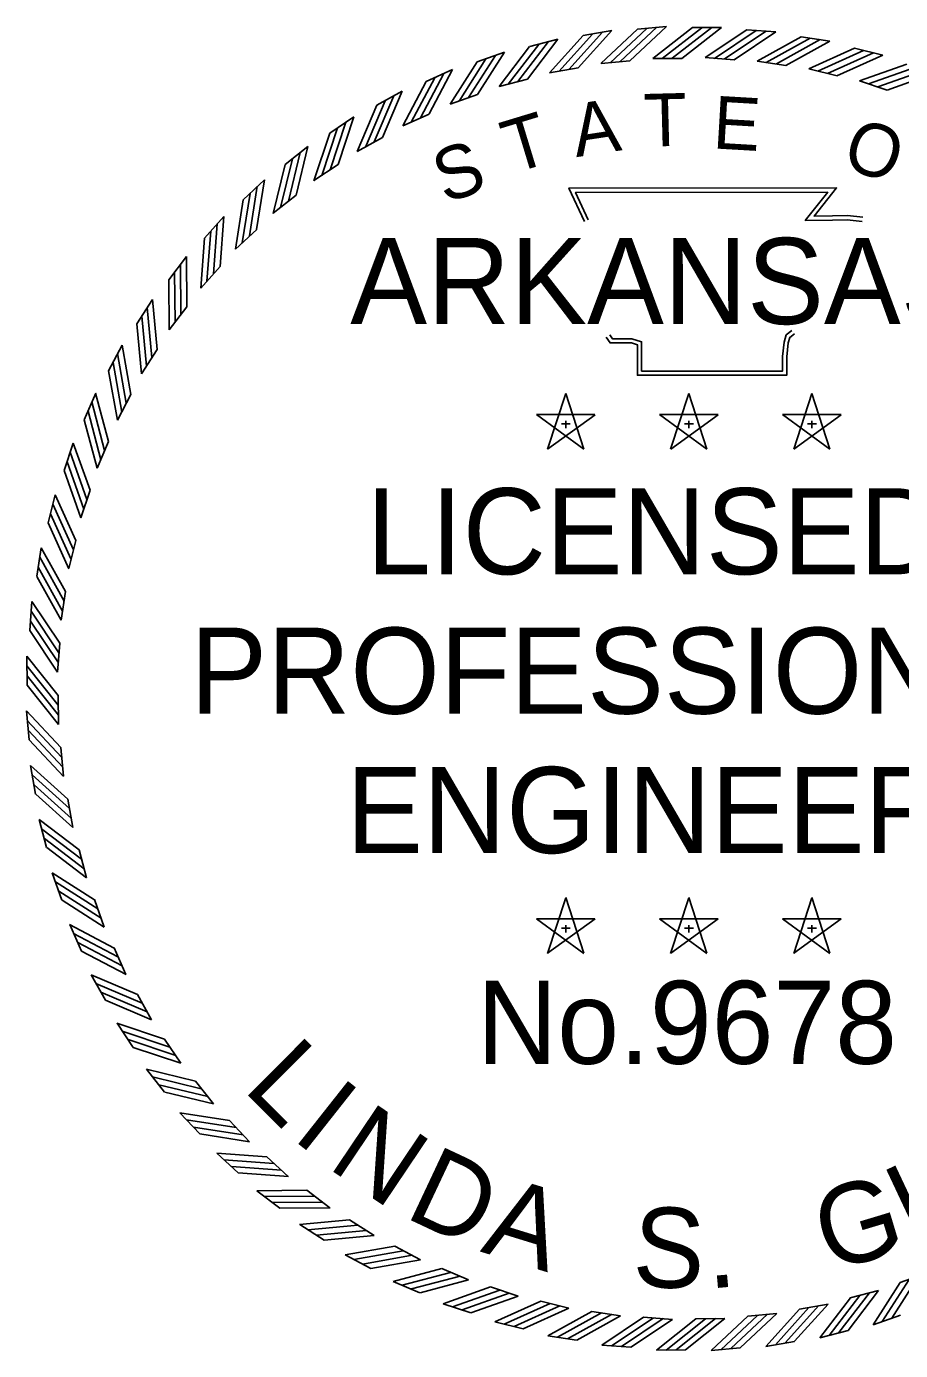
# Model space of a CAD drawing. Extents: x -35254 to 17396, y -8913 to 11592.
# Drawn here: x 8093 to 9735, y -5932 to -3444 of the extents above; entities that cross this region are included whole.
import ezdxf

# ---------------------------------------------------------------- set-up
doc = ezdxf.new("R2010")
doc.units = 0
doc.layers.add('STAMP', color=7, linetype='Continuous')

msp = doc.modelspace()

# ---------------------------------------------------------------- linework, layer by layer
at = {"layer": 'STAMP'}
for p, q in [((9138.8, -3461.1), (9192.4, -3451.6)), ((9240.8, -3448.9), (9295, -3443.9)), ((9343.9, -3445.8), (9398.4, -3445.8)), ((9446, -3449.9), (9500.3, -3453.9)), ((9038.2, -3481.6), (9090.9, -3467.8)), ((9547.9, -3463.2), (9601.7, -3471.6)), ((8939.6, -3510.4), (8990.9, -3492.3)), ((9269.6, -3503.8), (9324.2, -3503.8)), ((9367.6, -3502.3), (9422.1, -3506.3)), ((9648.3, -3484.7), (9701.2, -3497.6)), ((8843.7, -3547.3), (8893.4, -3524.9)), ((9075.6, -3531.1), (9129.4, -3521.6)), ((9172.1, -3513.4), (9226.4, -3508.4)), ((9465.4, -3508.9), (9519.3, -3517.4)), ((9562.3, -3523.5), (9615.4, -3536.4)), ((8981, -3556.6), (9033.8, -3542.7)), ((9657.7, -3546.1), (9709.5, -3563.3)), ((8751.2, -3591.9), (8798.9, -3565.5)), ((8888.8, -3589.9), (8940.3, -3571.7)), ((8662.7, -3644), (8708, -3613.8)), ((8799.7, -3630.7), (8849.5, -3608.3)), ((8714.2, -3678.6), (8762, -3652.2)), ((8578.8, -3703.3), (8621.5, -3669.4)), ((8633, -3733.5), (8678.4, -3703.2)), ((8500.1, -3769.3), (8539.9, -3732)), ((8556.6, -3794.9), (8599.4, -3761)), ((8427.1, -3841.5), (8463.6, -3801.1)), ((8485.5, -3862.4), (8525.4, -3825.1)), ((8360.3, -3919.6), (8393.4, -3876.3)), ((8420.3, -3935.6), (8456.9, -3895)), ((8300.2, -4002.8), (8329.6, -3957)), ((8361.3, -4013.8), (8394.4, -3970.4)), ((8247.2, -4090.8), (8272.7, -4042.7)), ((8309, -4096.7), (8338.4, -4050.7)), ((8201.6, -4182.8), (8223.1, -4132.7)), ((8263.7, -4183.6), (8289.2, -4135.4)), ((9105.9, -4133.3), (9071.8, -4237.9)), ((9139.8, -4237.8), (9105.9, -4133.2)), ((9337, -4133.3), (9302.9, -4237.9)), ((9370.9, -4237.8), (9337, -4133.2)), ((9568.1, -4133.3), (9534, -4237.9)), ((9602, -4237.8), (9568.2, -4133.2)), ((9160.8, -4173.2), (9050.8, -4173.1)), ((9050.9, -4173.2), (9139.8, -4238)), ((9071.9, -4237.8), (9160.9, -4173.3)), ((9391.9, -4173.2), (9281.9, -4173.1)), ((9282, -4173.2), (9370.9, -4238)), ((9303, -4237.8), (9392.1, -4173.3)), ((9623, -4173.2), (9513, -4173.1)), ((9513.1, -4173.2), (9602.1, -4238)), ((9534.1, -4237.8), (9623.2, -4173.3)), ((9098, -4190.8), (9114.4, -4190.8)), ((9106, -4184.9), (9106, -4198.7)), ((9329.1, -4190.8), (9345.5, -4190.8)), ((9337.1, -4184.9), (9337.1, -4198.7)), ((9560.2, -4190.8), (9576.6, -4190.8)), ((9568.2, -4184.9), (9568.2, -4198.7)), ((8163.8, -4278.3), (8181, -4226.6)), ((8225.7, -4274), (8247.2, -4223.8)), ((8134, -4376.6), (8146.9, -4323.7)), ((8195.3, -4367.2), (8212.6, -4315.4)), ((8112.4, -4477), (8120.9, -4423.2)), ((8172.7, -4462.6), (8185.7, -4409.5)), ((8099.2, -4578.9), (8103.2, -4524.5)), ((8158.1, -4559.5), (8166.6, -4505.6)), ((8094.4, -4681.5), (8093.9, -4627)), ((8151.5, -4657.3), (8155.6, -4602.8)), ((8153.1, -4755.3), (8152.6, -4700.7)), ((8098.1, -4784.1), (8093.1, -4729.9)), ((8162.7, -4852.8), (8157.7, -4798.5)), ((8110.3, -4886.1), (8100.9, -4832.4)), ((8180.3, -4949.3), (8170.8, -4895.5)), ((8130.9, -4986.7), (8117, -4934)), ((8205.9, -5043.9), (8192, -4991.1)), ((8159.7, -5085.3), (8141.5, -5033.9)), ((8239.1, -5136.1), (8220.9, -5084.6)), ((9105.9, -5080.9), (9071.8, -5185.5)), ((9139.8, -5185.4), (9105.9, -5080.8)), ((9337, -5080.9), (9302.9, -5185.5)), ((9370.9, -5185.4), (9337, -5080.8)), ((9568.1, -5080.9), (9534, -5185.5)), ((9602, -5185.4), (9568.2, -5080.8)), ((9160.8, -5120.8), (9050.8, -5120.7)), ((9050.9, -5120.8), (9139.8, -5185.6)), ((9071.9, -5185.4), (9160.9, -5120.9)), ((9391.9, -5120.8), (9281.9, -5120.7)), ((9282, -5120.8), (9370.9, -5185.6)), ((9303, -5185.4), (9392.1, -5120.9)), ((9623, -5120.8), (9513, -5120.7)), ((9513.1, -5120.8), (9602.1, -5185.6)), ((9534.1, -5185.4), (9623.2, -5120.9)), ((8196.5, -5181.2), (8174.2, -5131.5)), ((9098, -5138.4), (9114.4, -5138.4)), ((9106, -5132.5), (9106, -5146.3)), ((9329.1, -5138.4), (9345.5, -5138.4)), ((9337.1, -5132.5), (9337.1, -5146.3)), ((9560.2, -5138.4), (9576.6, -5138.4)), ((9568.2, -5132.5), (9568.2, -5146.3)), ((8279.9, -5225.2), (8257.5, -5175.4)), ((8241.2, -5273.7), (8214.8, -5226)), ((8327.9, -5310.7), (8301.5, -5262.9)), ((8293.3, -5362.2), (8263.1, -5316.8)), ((8382.8, -5391.9), (8352.5, -5346.5)), ((8352.5, -5446.1), (8318.7, -5403.4)), ((8444.2, -5468.3), (8410.2, -5425.5)), ((8418.5, -5524.8), (8381.3, -5485)), ((8511.7, -5539.4), (8474.3, -5499.5)), ((8490.8, -5597.8), (8450.4, -5561.2)), ((8584.8, -5604.6), (8544.3, -5568)), ((8568.8, -5664.6), (8525.5, -5631.5)), ((8663.1, -5663.6), (8619.7, -5630.5)), ((8652.1, -5724.7), (8606.2, -5695.3)), ((8746, -5715.9), (8700, -5686.5)), ((8832.9, -5761.2), (8784.6, -5735.7)), ((8740.1, -5777.7), (8691.9, -5752.2)), ((8923.3, -5799.2), (8873, -5777.7)), ((9785.3, -5785.8), (9733.8, -5804)), ((8832.1, -5823.3), (8782, -5801.8)), ((9016.4, -5829.6), (8964.6, -5812.3)), ((9693.1, -5819), (9640.3, -5832.9)), ((8927.6, -5861.1), (8875.9, -5843.9)), ((9111.8, -5852.2), (9058.8, -5839.2)), ((9598.5, -5844.6), (9544.7, -5854)), ((9208.7, -5866.8), (9154.8, -5858.3)), ((9306.5, -5873.3), (9252.1, -5869.3)), ((9502.1, -5862.2), (9447.7, -5867.2)), ((9734.6, -5865.2), (9683.2, -5883.4)), ((9025.9, -5890.9), (8972.9, -5878)), ((9404.5, -5871.8), (9349.9, -5872.3)), ((9636, -5894), (9583.3, -5907.9)), ((9126.3, -5912.5), (9072.5, -5904)), ((9535.4, -5914.6), (9481.7, -5924)), ((9228.1, -5925.7), (9173.8, -5921.7)), ((9330.7, -5930.5), (9276.2, -5931)), ((9433.4, -5926.8), (9379.1, -5931.8))]:
    msp.add_line(p, q, dxfattribs=at)
for points in [[(9092.9, -3528.3), (9156, -3458.2)], [(9111.4, -3524.6), (9174.6, -3454.5)], [(9129.3, -3521.6), (9192.5, -3451.6)], [(9172, -3513.5), (9240.7, -3448.9)], [(9189.5, -3512), (9258.2, -3447.5)], [(9208.3, -3509.9), (9277, -3445.3)], [(9226.4, -3508.4), (9295.1, -3443.8)], [(9269.5, -3503.9), (9343.9, -3445.9)], [(9287.1, -3504), (9361.4, -3446.1)], [(9306, -3503.6), (9380.3, -3445.6)], [(9324.1, -3503.8), (9398.5, -3445.8)], [(9367.5, -3502.3), (9445.9, -3450)], [(9385, -3503.8), (9463.4, -3451.4)], [(9403.9, -3504.8), (9482.3, -3452.4)], [(9422, -3506.3), (9500.4, -3453.9)], [(8981, -3556.7), (9038.1, -3481.7)], [(8998, -3552.4), (9055.1, -3477.4)], [(9016.2, -3547.2), (9073.3, -3472.2)], [(9033.8, -3542.7), (9090.9, -3467.7)], [(9075.6, -3531.1), (9138.7, -3461.1)], [(9465.3, -3508.9), (9547.8, -3463.2)], [(9482.6, -3511.8), (9565.1, -3466.1)], [(9501.4, -3514.3), (9583.8, -3468.6)], [(9519.3, -3517.3), (9601.7, -3471.6)], [(8905.4, -3584.3), (8956.1, -3504.8)], [(8923.1, -3577.6), (8973.8, -3498.1)], [(8940.2, -3571.7), (8991, -3492.2)], [(9562.2, -3523.5), (9648.2, -3484.8)], [(9579.2, -3527.8), (9665.2, -3489.1)], [(9597.7, -3531.9), (9683.7, -3493.2)], [(9615.3, -3536.4), (9701.3, -3497.6)], [(8832.8, -3615.5), (8876.8, -3532.2)], [(8849.4, -3608.2), (8893.4, -3524.9)], [(8888.8, -3590), (8939.5, -3510.5)], [(9657.6, -3546.1), (9746.5, -3514.6)], [(9674.2, -3551.8), (9763.1, -3520.3)], [(9692.3, -3557.4), (9781.1, -3525.9)], [(9709.5, -3563.3), (9798.3, -3531.7)], [(8799.6, -3630.7), (8843.7, -3547.4)], [(8815.7, -3623.7), (8859.7, -3540.3)], [(8746, -3660.8), (8782.9, -3574.1)], [(8761.9, -3652.2), (8798.9, -3565.5)], [(8714.2, -3678.7), (8751.2, -3592)], [(8729.6, -3670.4), (8766.6, -3583.7)], [(8663.2, -3713.2), (8692.9, -3623.7)], [(8678.4, -3703.2), (8708.1, -3613.8)], [(8633, -3733.6), (8662.7, -3644.1)], [(8647.7, -3724), (8677.4, -3634.5)], [(8585, -3772.1), (8607.2, -3680.5)], [(8599.3, -3761), (8621.5, -3669.4)], [(8556.6, -3795), (8578.8, -3703.4)], [(8570.4, -3784.2), (8592.6, -3692.6)], [(8511.9, -3837.4), (8526.5, -3744.2)], [(8525.3, -3825.1), (8539.9, -3731.9)], [(9140.9, -3810.5), (9111.9, -3747.6), (9614.4, -3747.3), (9572.4, -3800.1), (9606.6, -3799.6), (9635.1, -3799.3), (9663.6, -3802.4)], [(9148.2, -3807.2), (9124.3, -3755.6), (9597.9, -3755.3), (9555.8, -3808.2), (9606.7, -3807.6), (9634.7, -3807.2), (9662.7, -3810.3)], [(8485.5, -3862.5), (8500.1, -3769.4)], [(8498.4, -3850.6), (8513, -3757.5)], [(8456.8, -3895.1), (8463.6, -3801)], [(8432.1, -3922.7), (8439, -3828.7)], [(8444.5, -3908.4), (8451.4, -3814.4)], [(8420.3, -3935.6), (8427.1, -3841.6)], [(8394.4, -3970.5), (8393.4, -3876.2)], [(8372.1, -4000.1), (8371.1, -3905.8)], [(8383.2, -3984.8), (8382.3, -3890.5)], [(8361.3, -4013.9), (8360.3, -3919.7)], [(8328.4, -4066), (8319.7, -3972.1)], [(8338.3, -4050.8), (8329.6, -3956.9)], [(8309, -4096.8), (8300.2, -4002.9)], [(8318.6, -4082.1), (8309.8, -3988.3)], [(9535.2, -4021.1), (9526.7, -4028.1), (9523.8, -4038.5), (9521, -4064.5), (9521, -4099.3), (9240.5, -4099.3), (9240.5, -4052.4), (9240.5, -4042), (9229.1, -4038.5), (9189.2, -4038.5), (9182.1, -4027.7)], [(9530.2, -4014.9), (9519.7, -4023.5), (9516, -4037), (9513, -4064.1), (9513, -4091.3), (9248.4, -4091.3), (9248.4, -4052.4), (9248.4, -4036.1), (9230.3, -4030.5), (9193.5, -4030.5), (9188.7, -4023.3)], [(8289.1, -4135.4), (8272.7, -4042.6)], [(8272, -4168.3), (8255.6, -4075.5)], [(8280.5, -4151.4), (8264, -4058.6)], [(8263.7, -4183.7), (8247.2, -4090.9)], [(8239.8, -4240.5), (8215.7, -4149.3)], [(8247.1, -4223.8), (8223, -4132.7)], [(8232.8, -4258), (8208.7, -4166.9)], [(8225.7, -4274.1), (8201.6, -4182.9)], [(8212.5, -4315.4), (8181, -4226.6)], [(8206.6, -4332.6), (8175.1, -4243.7)], [(8195.3, -4367.3), (8163.8, -4278.4)], [(8201, -4350.7), (8169.5, -4261.8)], [(8185.6, -4409.6), (8146.9, -4323.6)], [(8181.1, -4427.2), (8142.4, -4341.2)], [(8172.8, -4462.7), (8134, -4376.7)], [(8177.1, -4445.7), (8138.3, -4359.7)], [(8166.6, -4505.6), (8120.8, -4423.2)], [(8163.6, -4523.5), (8117.9, -4441.1)], [(8158.2, -4559.6), (8112.4, -4477.1)], [(8161, -4542.3), (8115.3, -4459.8)], [(8155.5, -4602.9), (8103.1, -4524.5)], [(8154, -4621), (8101.6, -4542.6)], [(8153, -4639.9), (8100.7, -4561.5)], [(8151.6, -4657.4), (8099.2, -4579)], [(8152.5, -4700.8), (8093.9, -4626.9)], [(8152.5, -4718.9), (8093.9, -4645.1)], [(8153.1, -4737.8), (8094.5, -4664)], [(8153.1, -4755.4), (8094.5, -4681.6)], [(8157.6, -4798.5), (8093.1, -4729.8)], [(8159.1, -4816.6), (8094.6, -4747.9)], [(8161.3, -4835.4), (8096.7, -4766.7)], [(8162.7, -4852.9), (8098.2, -4784.2)], [(8170.8, -4895.5), (8100.8, -4832.4)], [(8173.8, -4913.4), (8103.8, -4850.3)], [(8177.5, -4932), (8107.5, -4868.9)], [(8180.4, -4949.3), (8110.4, -4886.2)], [(8192, -4991.1), (8117, -4934)], [(8196.4, -5008.7), (8121.4, -4951.6)], [(8201.6, -5026.9), (8126.6, -4969.8)], [(8205.9, -5043.9), (8131, -4986.8)], [(8220.9, -5084.7), (8141.5, -5033.9)], [(8226.8, -5101.8), (8147.4, -5051.1)], [(8233.5, -5119.5), (8154.1, -5068.8)], [(8239.2, -5136.1), (8159.8, -5085.4)], [(8257.5, -5175.5), (8174.1, -5131.5)], [(8264.8, -5192.1), (8181.4, -5148.1)], [(8272.9, -5209.2), (8189.6, -5165.2)], [(8280, -5225.3), (8196.6, -5181.2)], [(8301.5, -5263), (8214.7, -5226)], [(8310.1, -5278.9), (8223.4, -5241.9)], [(8319.6, -5295.3), (8232.9, -5258.3)], [(8328, -5310.7), (8241.3, -5273.7)], [(8352.5, -5346.5), (8263, -5316.8)], [(8362.4, -5361.7), (8272.9, -5332)], [(8373.3, -5377.2), (8283.8, -5347.5)], [(8382.9, -5391.9), (8293.4, -5362.2)], [(8410.2, -5425.6), (8318.6, -5403.4)], [(8421.4, -5439.9), (8329.8, -5417.7)], [(8433.5, -5454.5), (8341.9, -5432.3)], [(8444.3, -5468.3), (8352.6, -5446.1)], [(8474.3, -5499.6), (8381.2, -5485)], [(8486.6, -5513), (8393.5, -5498.4)], [(8499.9, -5526.5), (8406.7, -5511.9)], [(8511.8, -5539.4), (8418.6, -5524.8)], [(8544.3, -5568.1), (8450.3, -5561.2)], [(8557.7, -5580.4), (8463.6, -5573.5)], [(8572, -5592.7), (8478, -5585.9)], [(8584.9, -5604.6), (8490.9, -5597.8)], [(8619.7, -5630.5), (8525.4, -5631.5)], [(8634, -5641.7), (8539.8, -5642.6)], [(8649.3, -5652.8), (8555.1, -5653.8)], [(8663.2, -5663.6), (8568.9, -5664.6)], [(8700, -5686.5), (8606.1, -5695.3)], [(8715.2, -5696.5), (8621.3, -5705.2)], [(8731.4, -5706.3), (8637.5, -5715.1)], [(8746.1, -5715.9), (8652.2, -5724.7)], [(8784.7, -5735.7), (8691.8, -5752.2)], [(8800.6, -5744.4), (8707.8, -5760.8)], [(8817.6, -5752.9), (8724.7, -5769.3)], [(8833, -5761.2), (8740.1, -5777.7)], [(8873.1, -5777.8), (8781.9, -5801.9)], [(8889.7, -5785.1), (8798.6, -5809.1)], [(8907.3, -5792.1), (8816.1, -5816.2)], [(9768.8, -5791.4), (9718, -5870.8)], [(8923.3, -5799.2), (8832.2, -5823.3)], [(8964.7, -5812.4), (8875.8, -5843.9)], [(8981.9, -5818.3), (8893, -5849.8)], [(9693.2, -5819), (9636, -5893.9)], [(9733.9, -5804), (9683.2, -5883.4)], [(9751.1, -5798.1), (9700.3, -5877.5)], [(8999.9, -5823.9), (8911.1, -5855.4)], [(9016.5, -5829.5), (8927.7, -5861.1)], [(9058.8, -5839.3), (8972.9, -5878)], [(9076.4, -5843.7), (8990.5, -5882.5)], [(9598.6, -5844.5), (9535.4, -5914.5)], [(9640.4, -5832.9), (9583.2, -5907.9)], [(9658, -5828.5), (9600.8, -5903.5)], [(9676.2, -5823.3), (9619, -5898.2)], [(9094.9, -5847.8), (9009, -5886.6)], [(9111.9, -5852.1), (9026, -5890.9)], [(9154.9, -5858.3), (9072.4, -5904)], [(9172.8, -5861.3), (9090.3, -5907)], [(9191.5, -5863.9), (9109.1, -5909.6)], [(9208.8, -5866.7), (9126.4, -5912.5)], [(9252.1, -5869.4), (9173.7, -5921.7)], [(9270.2, -5870.9), (9191.8, -5923.2)], [(9447.8, -5867.2), (9379.1, -5931.8)], [(9465.9, -5865.7), (9397.2, -5930.3)], [(9484.7, -5863.6), (9416, -5928.2)], [(9502.2, -5862.1), (9433.4, -5926.7)], [(9544.8, -5854.1), (9481.7, -5924.1)], [(9562.7, -5851.1), (9499.6, -5921.1)], [(9581.3, -5847.4), (9518.1, -5917.4)], [(9289.1, -5871.9), (9210.7, -5924.2)], [(9306.6, -5873.3), (9228.2, -5925.7)], [(9350, -5872.4), (9276.2, -5931)], [(9368.2, -5872.4), (9294.3, -5931)], [(9387.1, -5871.8), (9313.3, -5930.4)], [(9404.6, -5871.8), (9330.8, -5930.4)]]:
    msp.add_lwpolyline(points, dxfattribs=at)

# ---------------------------------------------------------------- texts
for s, height, rotation, p in [('T', 99.1, 1.4789, (9253.6, -3669.8)), ('E', 99.1, 356.672, (9380.5, -3672.8)), ('T', 99.1, 16.9015, (9005.3, -3721)), ('A', 99.1, 8.6788, (9125.6, -3689.5)), ('O', 99.1, 341.2218, (9621.2, -3706.8)), ('S', 99.1, 19.7726, (8879.2, -3777.5)), ('L', 150.5, 315.1295, (8497.4, -5441)), ('I', 150.5, 321.696, (8589, -5532.1)), ('N', 150.5, 326.0736, (8655.6, -5586.8)), ('U', 150.5, 25.1712, (9758, -5735)), ('D', 150.5, 334.8288, (8800.2, -5680.1)), ('A', 150.5, 342.8544, (8943.9, -5745.5)), ('G', 150.5, 16.7808, (9600.8, -5785.2)), ('S', 150.5, 357.8112, (9230, -5811.2)), ('.', 150.5, 5.1072, (9373.5, -5815.8))]:
    msp.add_text(s, height=height, rotation=rotation, dxfattribs=at).set_placement(p)
for s, height, p in [('ARKANSAS', 161.78, (8701.1, -4003)), ('LICENSED', 161.78, (8731.9, -4473.2)), ('PROFESSIONAL', 161.779, (8400.7, -4735.2)), ('ENGINEER', 161.78, (8693.4, -4997.1)), ('No.9678', 156, (8939.3, -5393.1))]:
    msp.add_text(s, height=height, dxfattribs=at).set_placement(p)

doc.saveas('drawing.dxf')
